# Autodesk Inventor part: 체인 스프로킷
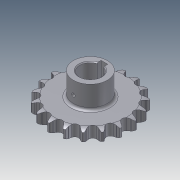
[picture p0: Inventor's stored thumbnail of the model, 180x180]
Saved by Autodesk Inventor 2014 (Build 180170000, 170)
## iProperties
Created: 2014-07
Part Number: 체인 스프로킷
Material: 강
Document SubType Name: Modeling
Designer: KYOUNG IL JANG
Density: 7.85 g/cm^3
Appearance: 강철
Mass: 738.599 g
Surface Area: 236.854 cm^2
Volume: 94.089 cm^3
CustomPartVersion: 1
Company: 한국ATC센터
Author: KYOUNG IL JANG
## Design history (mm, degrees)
sketch "이론적 톱니 프로파일"
  geometry: L1 (0, 0)-(0, 45.567); L2 (0, 0)-(14.795, 43.098); L3 (0, 45.567)-(14.795, 43.098); L4 (0, 45.567)-(5.661, 50.015); L5 (5.661, 50.015)-(-5.141, 45.406); L6 (-12.428, 43.493)-(-5.573, 46.417); L7 (-5.141, 45.406)-(-5.573, 46.417); L8 (5.573, 46.417)-(5.141, 45.406); L9 (0, 0)-(8.138, 48.771); A1 r 45.567 centre (0, 0) between (0, 45.567) and (14.795, 43.098); A2 r 49.445 centre (0, 0) between (7.302, 48.903) and (-7.302, 48.903); A3 r 4.545 centre (0, 45.567) between (-3.574, 42.758) and (3.574, 42.758); A4 r 7.453 centre (12.428, 43.493) between (7.302, 48.903) and (5.573, 46.417); A5 r 7.453 centre (-12.428, 43.493) between (-5.573, 46.417) and (-7.302, 48.903); A6 r 11.745 centre (5.661, 50.015) between (-5.141, 45.406) and (-3.574, 42.758); A7 r 11.745 centre (-5.661, 50.015) between (3.574, 42.758) and (5.141, 45.406); 2 further points
  constraints: 18 end point, 15 point on circle, 7 centre point, 3 coincident, 3 point on line, 3 symmetric about line, 3 tangent, 1 equal radius, 1 midpoint, 1 parallel, 1 vertical, 1 other
  dimensions: "d0" = 91.13301 diameter of A1 (computed from da_p, da_z); "d2" = 18.9474 deg angle of L2 L1 (computed from da_z); "d3" = 4.545 radius of A3 (= 0.5 x da_Dr + da_SC); "d10" = 128.158 deg angle of L4 L1 (computed from da_z); "d11" = 15.0526 deg angle of L5 L4 (computed from da_z); "d12" = 7.2 distance of L3.start L4.end (= 0.8 x da_Dr); "d13" = 11.745 distance of L4.end L5.end (= 1.3 x da_Dr + da_SC); "d14" = 12.6 distance of A4.centre L1.end (= 1.4 x da_Dr); "d23" = 4.5 distance from line of L9.end L3 (= da_Ha)
sketch "톱니 프로파일"
  geometry: L1 (0, 0)-(0, 45.567); L2 (0, 45.567)-(4.203, 43.837); L3 (0, 45.567)-(-4.203, 43.837); A1 r 4.545 centre (0, 45.567) between (-4.203, 43.837) and (4.203, 43.837); A2 r 22.68 centre (25.176, 35.206) between (7.12, 48.93) and (4.203, 43.837); A3 r 22.68 centre (-25.176, 35.206) between (-4.203, 43.837) and (-7.12, 48.93); A4 r 49.445 centre (0, 0) between (-7.12, 48.93) and (7.12, 48.93) reference; 1 further point
  constraints: 9 point on circle, 6 end point, 3 centre point, 2 tangent, 1 coincident, 1 equal radius, 1 vertical, 1 other
  dimensions: "d44" = 135.263 deg angle of L3 L2 (= da_Alfa); "d45" = 22.68 radius of A2 (= da_Re); "d46" = 4.545 radius of A1 (= da_Ri)
sketch "단면 프로파일"
  geometry: L1 (49.445, 0)-(-49.445, 0) reference; L2 (33.265, 6.65)-(-33.265, 6.65); L3 (-33.265, 6.65)-(-33.265, -6.65); L4 (-33.265, -6.65)-(33.265, -6.65); L5 (33.265, -6.65)-(33.265, 6.65); L6 (33.265, 6.65)-(49.445, 6.65); L7 (49.445, 6.65)-(49.445, -6.65); L8 (49.445, -6.65)-(33.265, -6.65); L9 (33.265, -6.65)-(33.265, 6.65); L10 (42.183, 6.65)-(0, 6.65); L11 (0, 6.65)-(0, -6.65); L12 (0, -6.65)-(42.183, -6.65); L13 (0, 6.65)-(0, -6.65); L14 (49.445, 4.775)-(49.445, -4.775); A1 r 15 centre (42.183, -8.35) between (49.445, 4.775) and (42.183, 6.65); A2 r 15 centre (42.183, 8.35) between (42.183, -6.65) and (49.445, -4.775); 2 further points
  constraints: 26 end point, 7 midpoint, 5 perpendicular, 4 parallel, 4 point on circle, 3 point on line, 3 symmetric about line, 2 centre point, 2 horizontal, 2 tangent, 1 collinear, 1 other
  dimensions: "d30" = 13.3 distance between parallel lines of L8 L6 (= da_Bf); "d31" = 66.53007 distance between parallel lines of L3 L5 (= da_Ds); "d32" = 13.3 distance between parallel lines of L4 L2 (= da_Bs); "d33" = 1.875 distance from line of L14.start L6 (= da_Ba); "d34" = 15 radius of A1 (= da_Rx); "d43" = 6.65 distance between parallel lines of L4 L1 (computed from da_k, da_pt, da_Bs)
revolve "슈라우드" stored, may be unused: angle "d36" = 90 deg
revolve "스트랜드" stored, may be unused: angle "d37" = 90 deg
extrude "이론적 톱니" cut sketch "이론적 톱니 프로파일" stored distance "d18" = 10; taper "d19" = 0 deg; dims "d49" = 0, "form_type" = 0 [user parameter]
extrude "톱니" cut sketch "톱니 프로파일" stored distance "d47" = 10; taper "d48" = 0 deg; dims "d50" = 10, "form_type" = 0 [user parameter]
node "타이밍 평면"
node "작업 평면3"
sketch "스케치5"
  geometry: C1 r 20 at (0, -45.567); 1 further point
  constraints: 1 centre point, 1 coincident
  dimensions: "d52" = 40 diameter of C1
extrude "돌출4" join sketch "스케치5" stored distance "d53" = 10; taper "d54" = 0 deg
sketch "스케치6"
  geometry: L1 (4, 11.843)-(4, 16.5); L2 (4, 16.5)-(-4, 16.5); L3 (-4, 16.5)-(-4, 11.843); A1 r 12.5 centre (0, 0) between (4, 11.843) and (-4, 11.843); 1 further point
  constraints: 6 end point, 2 parallel, 2 point on circle, 1 centre point, 1 coincident, 1 perpendicular, 1 vertical
  dimensions: "d55" = 25 diameter of A1; "d56" = 29 dimension on A1 L2 (computed from d55); "d57" = 8 distance of L1.end L2.end
extrude "돌출5" cut sketch "스케치6" stored distance "d58" = 10; taper "d59" = 0 deg
fillet "모깎기2" dims "d60" = 3
chamfer "모따기1" distance "d61" = 1; stored, may be unused: second distance "d62" = 2, angle "d63" = 45 deg
node "작업 평면4"
sketch "스케치7"
  geometry: L1 (-13.5, -13.3)-(13.5, -13.3) reference; 4 further points
  constraints: 1 vertical alignment
  dimensions: "d65" = 25 distance from line of point (0, 11.7) L1
hole "구멍1" sketch "스케치7" at (0, 11.7) diameter "d66" = 4.134; stored, may be unused: countersink angle "d70" = 90 deg, drill point angle "d72" = 118 deg; dims "d67" = 6, "d68" = 4, "d69" = 2, "d71" = 8
body "Solid1"
pattern_linear "스트랜드 패턴" dims "d40" = 24 (= da_pt)
pattern_circular "톱니 패턴" dims angle "d21" = 360 deg
other parameters: "da_p" = 15 [user parameter; used in 1 equation term], "da_Dr" = 9 [user parameter; used in 4 equation terms], "da_SC" = 0.045 [user parameter; used in 2 equation terms], "da_Ha" = 4.5 [user parameter; used in 1 equation term], "da_pt" = 24 [user parameter; used in 2 equation terms], "da_Bf" = 13.3 [user parameter; used in 1 equation term], "d28" = 0, "d29" = 0, "da_Ba" = 1.875 [user parameter; used in 1 equation term], "da_Rx" = 15 [user parameter; used in 1 equation term], "da_Ra" = 0.6 [user parameter], "da_Bs" = 13.3 [user parameter; used in 2 equation terms], "da_Ds" = 66.53007 [user parameter; used in 1 equation term], "d42" = 0, "da_Re" = 22.68 [user parameter; used in 1 equation term], "da_Ri" = 4.545 [user parameter; used in 1 equation term], "da_Alfa" = 135.263 deg [user parameter; used in 1 equation term]
